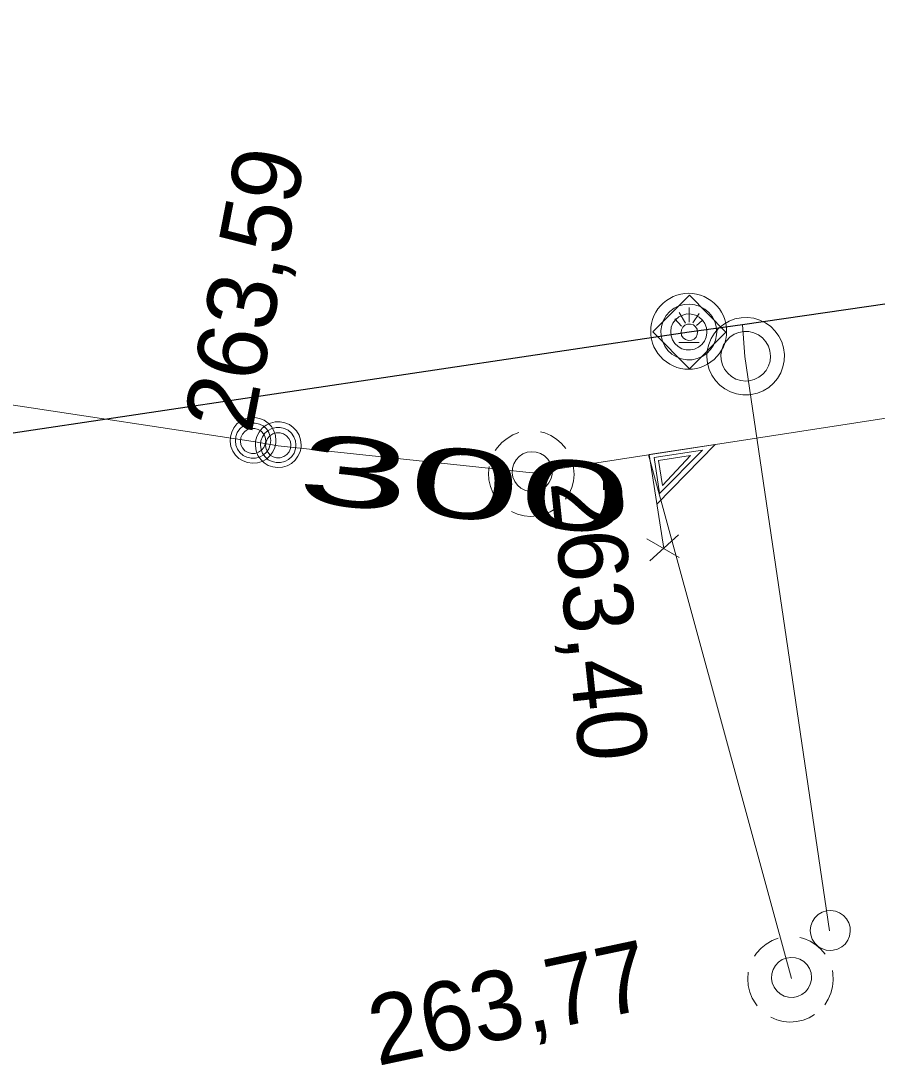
# Model space of a CAD drawing. Extents: x -732096 to -731933, y -1048703 to -1047964.
# Drawn here: x -732040.41 to -732030.53, y -1048320.38 to -1048308.34 of the extents above; entities that cross this region are included whole.
import ezdxf

# ---------------------------------------------------------------- set-up
doc = ezdxf.new("R2010")
doc.units = 0
doc.header["$LTSCALE"] = 0.32
doc.layers.add('1', color=7, linetype='Continuous')
for name, color, linetype, lineweight in [('18', 7, 'Continuous', 13), ('20', 7, 'Continuous', 13), ('49', 7, 'Continuous', 13), ('8', 7, 'Continuous', 13)]:
    doc.layers.add(name, color=color, linetype=linetype, lineweight=lineweight)

msp = doc.modelspace()

# ---------------------------------------------------------------- linework, layer by layer
at = {"layer": '18'}
for p, q in [((-732032.816, -1048314.526), (-732033.188, -1048314.311)), ((-732033.152, -1048314.565), (-732032.823, -1048314.268))]:
    msp.add_line(p, q, dxfattribs=at)
for points in [[(-732037.466, -1048313.177), (-732037.472, -1048313.121), (-732037.489, -1048313.068), (-732037.517, -1048313.019), (-732037.556, -1048312.978), (-732037.602, -1048312.946), (-732037.654, -1048312.924), (-732037.709, -1048312.913), (-732037.765, -1048312.915), (-732037.82, -1048312.928), (-732037.87, -1048312.953), (-732037.915, -1048312.988), (-732037.951, -1048313.031), (-732037.976, -1048313.081), (-732037.991, -1048313.136), (-732037.994, -1048313.192), (-732037.985, -1048313.247), (-732037.964, -1048313.3), (-732037.933, -1048313.346), (-732037.892, -1048313.385), (-732037.845, -1048313.415), (-732037.792, -1048313.434), (-732037.736, -1048313.441), (-732037.679, -1048313.437), (-732037.625, -1048313.42), (-732037.576, -1048313.393), (-732037.535, -1048313.355), (-732037.502, -1048313.31), (-732037.478, -1048313.259), (-732037.467, -1048313.204)], [(-732037.525, -1048313.18), (-732037.531, -1048313.131), (-732037.549, -1048313.085), (-732037.576, -1048313.044), (-732037.614, -1048313.011), (-732037.657, -1048312.989), (-732037.706, -1048312.977), (-732037.755, -1048312.977), (-732037.803, -1048312.989), (-732037.847, -1048313.012), (-732037.884, -1048313.045), (-732037.912, -1048313.086), (-732037.929, -1048313.133), (-732037.934, -1048313.182), (-732037.928, -1048313.231), (-732037.91, -1048313.277), (-732037.882, -1048313.317), (-732037.845, -1048313.35), (-732037.801, -1048313.372), (-732037.752, -1048313.384), (-732037.703, -1048313.383), (-732037.655, -1048313.371), (-732037.612, -1048313.347), (-732037.575, -1048313.314), (-732037.547, -1048313.273), (-732037.531, -1048313.226)], [(-732037.584, -1048313.184), (-732037.59, -1048313.142), (-732037.607, -1048313.104), (-732037.635, -1048313.073), (-732037.669, -1048313.05), (-732037.71, -1048313.039), (-732037.752, -1048313.039), (-732037.792, -1048313.051), (-732037.826, -1048313.074), (-732037.853, -1048313.106), (-732037.87, -1048313.144), (-732037.875, -1048313.185), (-732037.87, -1048313.227), (-732037.852, -1048313.264), (-732037.824, -1048313.296), (-732037.788, -1048313.318), (-732037.748, -1048313.329), (-732037.706, -1048313.328), (-732037.666, -1048313.315), (-732037.632, -1048313.292), (-732037.605, -1048313.259), (-732037.589, -1048313.221)], [(-732037.176, -1048313.227), (-732037.181, -1048313.171), (-732037.198, -1048313.118), (-732037.227, -1048313.069), (-732037.266, -1048313.028), (-732037.311, -1048312.996), (-732037.364, -1048312.974), (-732037.419, -1048312.963), (-732037.475, -1048312.965), (-732037.529, -1048312.978), (-732037.58, -1048313.003), (-732037.625, -1048313.038), (-732037.661, -1048313.081), (-732037.686, -1048313.131), (-732037.701, -1048313.186), (-732037.703, -1048313.242), (-732037.695, -1048313.297), (-732037.674, -1048313.35), (-732037.642, -1048313.396), (-732037.602, -1048313.435), (-732037.554, -1048313.465), (-732037.502, -1048313.484), (-732037.446, -1048313.491), (-732037.389, -1048313.487), (-732037.335, -1048313.47), (-732037.286, -1048313.443), (-732037.245, -1048313.405), (-732037.212, -1048313.36), (-732037.188, -1048313.309), (-732037.176, -1048313.254)], [(-732037.235, -1048313.23), (-732037.24, -1048313.181), (-732037.259, -1048313.135), (-732037.286, -1048313.094), (-732037.323, -1048313.061), (-732037.367, -1048313.039), (-732037.416, -1048313.027), (-732037.465, -1048313.027), (-732037.512, -1048313.039), (-732037.556, -1048313.062), (-732037.593, -1048313.095), (-732037.622, -1048313.136), (-732037.639, -1048313.183), (-732037.644, -1048313.232), (-732037.637, -1048313.281), (-732037.62, -1048313.327), (-732037.592, -1048313.367), (-732037.554, -1048313.4), (-732037.511, -1048313.422), (-732037.462, -1048313.434), (-732037.413, -1048313.433), (-732037.365, -1048313.421), (-732037.321, -1048313.397), (-732037.284, -1048313.364), (-732037.257, -1048313.323), (-732037.24, -1048313.276)], [(-732037.294, -1048313.234), (-732037.299, -1048313.192), (-732037.316, -1048313.154), (-732037.345, -1048313.123), (-732037.379, -1048313.1), (-732037.419, -1048313.089), (-732037.462, -1048313.089), (-732037.502, -1048313.101), (-732037.536, -1048313.124), (-732037.563, -1048313.156), (-732037.58, -1048313.194), (-732037.585, -1048313.235), (-732037.58, -1048313.277), (-732037.561, -1048313.314), (-732037.534, -1048313.346), (-732037.497, -1048313.368), (-732037.458, -1048313.379), (-732037.416, -1048313.378), (-732037.375, -1048313.365), (-732037.342, -1048313.342), (-732037.315, -1048313.309), (-732037.299, -1048313.271)], [(-732034.279, -1048313.539), (-732034.285, -1048313.487), (-732034.303, -1048313.437), (-732034.331, -1048313.393), (-732034.369, -1048313.356), (-732034.414, -1048313.329), (-732034.464, -1048313.313), (-732034.516, -1048313.308), (-732034.568, -1048313.315), (-732034.617, -1048313.334), (-732034.661, -1048313.364), (-732034.696, -1048313.403), (-732034.722, -1048313.448), (-732034.737, -1048313.499), (-732034.74, -1048313.551), (-732034.732, -1048313.603), (-732034.711, -1048313.651), (-732034.681, -1048313.694), (-732034.641, -1048313.729), (-732034.595, -1048313.753), (-732034.544, -1048313.767), (-732034.492, -1048313.769), (-732034.44, -1048313.759), (-732034.392, -1048313.737), (-732034.35, -1048313.705), (-732034.317, -1048313.665), (-732034.293, -1048313.618), (-732034.281, -1048313.567)], [(-732031.289, -1048319.369), (-732031.295, -1048319.317), (-732031.313, -1048319.267), (-732031.341, -1048319.223), (-732031.379, -1048319.186), (-732031.424, -1048319.159), (-732031.474, -1048319.143), (-732031.526, -1048319.138), (-732031.578, -1048319.145), (-732031.627, -1048319.164), (-732031.671, -1048319.194), (-732031.706, -1048319.233), (-732031.732, -1048319.278), (-732031.747, -1048319.329), (-732031.75, -1048319.381), (-732031.742, -1048319.433), (-732031.721, -1048319.481), (-732031.691, -1048319.524), (-732031.651, -1048319.559), (-732031.605, -1048319.583), (-732031.554, -1048319.597), (-732031.502, -1048319.599), (-732031.45, -1048319.589), (-732031.402, -1048319.567), (-732031.36, -1048319.535), (-732031.327, -1048319.495), (-732031.303, -1048319.448), (-732031.291, -1048319.397)]]:
    msp.add_lwpolyline(points, close=True, dxfattribs=at)
for points in [[(-732034.663, -1048313.087), (-732034.734, -1048313.115), (-732034.801, -1048313.154), (-732034.861, -1048313.202), (-732034.912, -1048313.259), (-732034.936, -1048313.293)], [(-732034.122, -1048313.27), (-732034.172, -1048313.212), (-732034.23, -1048313.162), (-732034.295, -1048313.121), (-732034.366, -1048313.092), (-732034.415, -1048313.078)], [(-732032.994, -1048314.422), (-732033.161, -1048313.34), (-732032.4, -1048313.223), (-732033.073, -1048313.912)], [(-732033.041, -1048313.786), (-732033.105, -1048313.376), (-732032.545, -1048313.29), (-732033.041, -1048313.788)], [(-732033.008, -1048313.697), (-732033.052, -1048313.408), (-732032.684, -1048313.352), (-732033.009, -1048313.697)], [(-732035.008, -1048313.479), (-732035.014, -1048313.556), (-732035.009, -1048313.633), (-732034.992, -1048313.708), (-732034.963, -1048313.779), (-732034.923, -1048313.845), (-732034.907, -1048313.867)], [(-732034.127, -1048313.856), (-732034.086, -1048313.791), (-732034.055, -1048313.721), (-732034.036, -1048313.646), (-732034.028, -1048313.57), (-732034.033, -1048313.493), (-732034.039, -1048313.458)], [(-732034.75, -1048313.996), (-732034.68, -1048314.027), (-732034.605, -1048314.046), (-732034.529, -1048314.053), (-732034.452, -1048314.048), (-732034.377, -1048314.031), (-732034.305, -1048314.003), (-732034.245, -1048313.968)], [(-732031.673, -1048318.917), (-732031.744, -1048318.945), (-732031.811, -1048318.984), (-732031.871, -1048319.032), (-732031.922, -1048319.089), (-732031.946, -1048319.123)], [(-732031.132, -1048319.1), (-732031.182, -1048319.042), (-732031.24, -1048318.992), (-732031.305, -1048318.951), (-732031.376, -1048318.922), (-732031.425, -1048318.908)], [(-732032.018, -1048319.309), (-732032.024, -1048319.386), (-732032.019, -1048319.463), (-732032.002, -1048319.538), (-732031.973, -1048319.609), (-732031.933, -1048319.675), (-732031.917, -1048319.697)], [(-732031.137, -1048319.686), (-732031.096, -1048319.621), (-732031.065, -1048319.551), (-732031.046, -1048319.476), (-732031.038, -1048319.4), (-732031.043, -1048319.323), (-732031.049, -1048319.288)], [(-732031.76, -1048319.826), (-732031.69, -1048319.857), (-732031.615, -1048319.876), (-732031.539, -1048319.883), (-732031.462, -1048319.878), (-732031.387, -1048319.861), (-732031.315, -1048319.833), (-732031.255, -1048319.798)]]:
    msp.add_lwpolyline(points, dxfattribs=at)
at = {"layer": '20'}
msp.add_lwpolyline([(-732034.51, -1048313.55), (-732033.17, -1048313.344), (-732030.204, -1048312.887), (-732020.123, -1048311.336), (-732008.47, -1048309.542)], dxfattribs=at)
msp.add_lwpolyline([(-732034.51, -1048313.55), (-732033.17, -1048313.344), (-732030.204, -1048312.887), (-732020.123, -1048311.336), (-732008.47, -1048309.542)], dxfattribs=at)
at = {"layer": '49'}
for p, q in [((-732056.5, -1048310.35), (-732037.73, -1048313.19)), ((-732056.5, -1048310.35), (-732037.73, -1048313.19)), ((-732031.52, -1048319.38), (-732033.17, -1048313.344)), ((-732031.52, -1048319.38), (-732033.17, -1048313.344))]:
    msp.add_line(p, q, dxfattribs=at)
msp.add_lwpolyline([(-732037.73, -1048313.19), (-732037.44, -1048313.24), (-732034.51, -1048313.55)], dxfattribs=at)
msp.add_lwpolyline([(-732037.73, -1048313.19), (-732037.44, -1048313.24), (-732034.51, -1048313.55)], dxfattribs=at)
at = {"layer": '8'}
for p, q in [((-732032.816, -1048311.704), (-732032.744, -1048311.825)), ((-732032.702, -1048311.646), (-732032.702, -1048311.815)), ((-732032.656, -1048311.823), (-732032.585, -1048311.716)), ((-732032.864, -1048311.776), (-732032.788, -1048311.859)), ((-732032.616, -1048311.852), (-732032.552, -1048311.794)), ((-732032.821, -1048312.049), (-732032.586, -1048312.049))]:
    msp.add_line(p, q, dxfattribs=at)
at = {"layer": '8', "lineweight": 25}
msp.add_line((-732032.699, -1048311.93), (-732040.93, -1048313.16), dxfattribs=at)
msp.add_lwpolyline([(-732008.203, -1048308.341), (-732012.035, -1048308.931), (-732012.542, -1048309.009), (-732021.995, -1048310.381), (-732032.087, -1048311.846), (-732032.699, -1048311.93)], dxfattribs=at)
at = {"layer": '8'}
for points in [[(-732032.269, -1048311.919), (-732032.271, -1048311.874), (-732032.278, -1048311.829), (-732032.29, -1048311.784), (-732032.306, -1048311.742), (-732032.327, -1048311.701), (-732032.352, -1048311.662), (-732032.381, -1048311.627), (-732032.413, -1048311.594), (-732032.449, -1048311.566), (-732032.487, -1048311.541), (-732032.528, -1048311.52), (-732032.571, -1048311.503), (-732032.615, -1048311.491), (-732032.66, -1048311.484), (-732032.706, -1048311.482), (-732032.752, -1048311.484), (-732032.797, -1048311.491), (-732032.841, -1048311.503), (-732032.884, -1048311.52), (-732032.925, -1048311.541), (-732032.963, -1048311.566), (-732032.999, -1048311.594), (-732033.031, -1048311.627), (-732033.06, -1048311.662), (-732033.085, -1048311.701), (-732033.106, -1048311.742), (-732033.122, -1048311.784), (-732033.134, -1048311.829), (-732033.141, -1048311.874), (-732033.144, -1048311.92), (-732033.141, -1048311.965), (-732033.134, -1048312.01), (-732033.122, -1048312.055), (-732033.106, -1048312.097), (-732033.085, -1048312.138), (-732033.06, -1048312.177), (-732033.031, -1048312.212), (-732032.999, -1048312.245), (-732032.963, -1048312.273), (-732032.925, -1048312.298), (-732032.884, -1048312.319), (-732032.841, -1048312.336), (-732032.797, -1048312.347), (-732032.752, -1048312.355), (-732032.706, -1048312.357), (-732032.66, -1048312.355), (-732032.615, -1048312.347), (-732032.571, -1048312.336), (-732032.528, -1048312.319), (-732032.487, -1048312.298), (-732032.449, -1048312.273), (-732032.413, -1048312.245), (-732032.381, -1048312.212), (-732032.352, -1048312.177), (-732032.327, -1048312.138), (-732032.306, -1048312.097), (-732032.29, -1048312.055), (-732032.278, -1048312.01), (-732032.271, -1048311.965), (-732032.269, -1048311.92)], [(-732033.119, -1048311.926), (-732032.698, -1048311.505), (-732032.276, -1048311.928), (-732032.697, -1048312.351), (-732033.118, -1048311.926)], [(-732032.087, -1048311.846), (-732032.059, -1048312.21), (-732031.083, -1048318.831)]]:
    msp.add_lwpolyline(points, dxfattribs=at)
for points in [[(-732032.382, -1048311.927), (-732032.388, -1048311.866), (-732032.406, -1048311.806), (-732032.435, -1048311.751), (-732032.474, -1048311.703), (-732032.521, -1048311.663), (-732032.575, -1048311.633), (-732032.634, -1048311.613), (-732032.696, -1048311.606), (-732032.758, -1048311.61), (-732032.818, -1048311.626), (-732032.873, -1048311.654), (-732032.923, -1048311.691), (-732032.964, -1048311.738), (-732032.996, -1048311.791), (-732033.016, -1048311.85), (-732033.026, -1048311.911), (-732033.023, -1048311.973), (-732033.008, -1048312.033), (-732032.982, -1048312.09), (-732032.946, -1048312.14), (-732032.9, -1048312.183), (-732032.848, -1048312.215), (-732032.79, -1048312.238), (-732032.729, -1048312.248), (-732032.667, -1048312.247), (-732032.606, -1048312.234), (-732032.549, -1048312.209), (-732032.498, -1048312.174), (-732032.454, -1048312.13), (-732032.42, -1048312.078), (-732032.396, -1048312.021), (-732032.384, -1048311.96)], [(-732032.496, -1048311.927), (-732032.502, -1048311.878), (-732032.519, -1048311.831), (-732032.547, -1048311.79), (-732032.585, -1048311.757), (-732032.629, -1048311.733), (-732032.677, -1048311.721), (-732032.727, -1048311.72), (-732032.775, -1048311.732), (-732032.82, -1048311.754), (-732032.858, -1048311.787), (-732032.887, -1048311.827), (-732032.906, -1048311.874), (-732032.913, -1048311.923), (-732032.908, -1048311.973), (-732032.891, -1048312.02), (-732032.864, -1048312.062), (-732032.827, -1048312.096), (-732032.784, -1048312.12), (-732032.736, -1048312.134), (-732032.686, -1048312.135), (-732032.637, -1048312.125), (-732032.592, -1048312.103), (-732032.553, -1048312.071), (-732032.523, -1048312.032), (-732032.504, -1048311.986), (-732032.496, -1048311.936)], [(-732032.603, -1048311.93), (-732032.609, -1048311.897), (-732032.626, -1048311.868), (-732032.652, -1048311.847), (-732032.684, -1048311.836), (-732032.718, -1048311.837), (-732032.749, -1048311.849), (-732032.774, -1048311.872), (-732032.79, -1048311.901), (-732032.794, -1048311.935), (-732032.787, -1048311.968), (-732032.768, -1048311.996), (-732032.741, -1048312.016), (-732032.709, -1048312.026), (-732032.675, -1048312.023), (-732032.644, -1048312.009), (-732032.62, -1048311.986), (-732032.606, -1048311.955)], [(-732031.984, -1048312.649), (-732031.913, -1048312.633), (-732031.845, -1048312.605), (-732031.783, -1048312.567), (-732031.728, -1048312.518), (-732031.681, -1048312.462), (-732031.644, -1048312.399), (-732031.619, -1048312.331), (-732031.604, -1048312.259), (-732031.602, -1048312.186), (-732031.611, -1048312.112), (-732031.632, -1048312.043), (-732031.665, -1048311.977), (-732031.707, -1048311.918), (-732031.759, -1048311.866), (-732031.819, -1048311.823), (-732031.884, -1048311.791), (-732031.955, -1048311.77), (-732032.027, -1048311.76), (-732032.1, -1048311.763), (-732032.172, -1048311.777), (-732032.24, -1048311.803), (-732032.303, -1048311.84), (-732032.36, -1048311.887), (-732032.408, -1048311.942), (-732032.446, -1048312.004), (-732032.474, -1048312.072), (-732032.491, -1048312.143), (-732032.495, -1048312.216), (-732032.488, -1048312.289), (-732032.469, -1048312.36), (-732032.438, -1048312.426), (-732032.397, -1048312.487), (-732032.346, -1048312.54), (-732032.288, -1048312.584), (-732032.223, -1048312.618), (-732032.154, -1048312.642), (-732032.082, -1048312.652), (-732032.009, -1048312.652)], [(-732032.007, -1048312.49), (-732031.951, -1048312.476), (-732031.898, -1048312.45), (-732031.851, -1048312.415), (-732031.813, -1048312.37), (-732031.784, -1048312.319), (-732031.767, -1048312.263), (-732031.761, -1048312.205), (-732031.768, -1048312.146), (-732031.786, -1048312.091), (-732031.816, -1048312.04), (-732031.854, -1048311.996), (-732031.901, -1048311.961), (-732031.954, -1048311.937), (-732032.012, -1048311.923), (-732032.069, -1048311.921), (-732032.127, -1048311.932), (-732032.182, -1048311.954), (-732032.231, -1048311.986), (-732032.271, -1048312.028), (-732032.303, -1048312.077), (-732032.324, -1048312.132), (-732032.334, -1048312.19), (-732032.331, -1048312.248), (-732032.317, -1048312.305), (-732032.292, -1048312.358), (-732032.256, -1048312.404), (-732032.211, -1048312.442), (-732032.161, -1048312.47), (-732032.104, -1048312.487), (-732032.046, -1048312.493)], [(-732031.038, -1048319.056), (-732030.988, -1048319.043), (-732030.941, -1048319.018), (-732030.902, -1048318.984), (-732030.87, -1048318.941), (-732030.85, -1048318.892), (-732030.842, -1048318.84), (-732030.844, -1048318.788), (-732030.859, -1048318.738), (-732030.885, -1048318.692), (-732030.921, -1048318.653), (-732030.965, -1048318.624), (-732031.013, -1048318.605), (-732031.066, -1048318.598), (-732031.118, -1048318.602), (-732031.168, -1048318.618), (-732031.212, -1048318.645), (-732031.25, -1048318.681), (-732031.279, -1048318.726), (-732031.296, -1048318.775), (-732031.303, -1048318.828), (-732031.297, -1048318.879), (-732031.28, -1048318.929), (-732031.251, -1048318.974), (-732031.213, -1048319.011), (-732031.169, -1048319.037), (-732031.119, -1048319.054), (-732031.066, -1048319.059)]]:
    msp.add_lwpolyline(points, close=True, dxfattribs=at)

# ---------------------------------------------------------------- texts
at = {"layer": '1'}
for s, rotation, p in [('263,59', 79, (-732037.748, -1048313.113)), ('263,40', 276, (-732034.3, -1048313.657)), ('263,77', 12, (-732036.296, -1048320.391))]:
    msp.add_text(s, height=0.8, rotation=rotation, dxfattribs=at).set_placement(p)
at = {"layer": '1', "width": 2.15}
msp.add_text('300 ', height=0.8, rotation=354, dxfattribs=at).set_placement((-732037.241, -1048313.876))

doc.saveas('drawing.dxf')
